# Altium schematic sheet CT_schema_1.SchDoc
size 612 x 583 mm
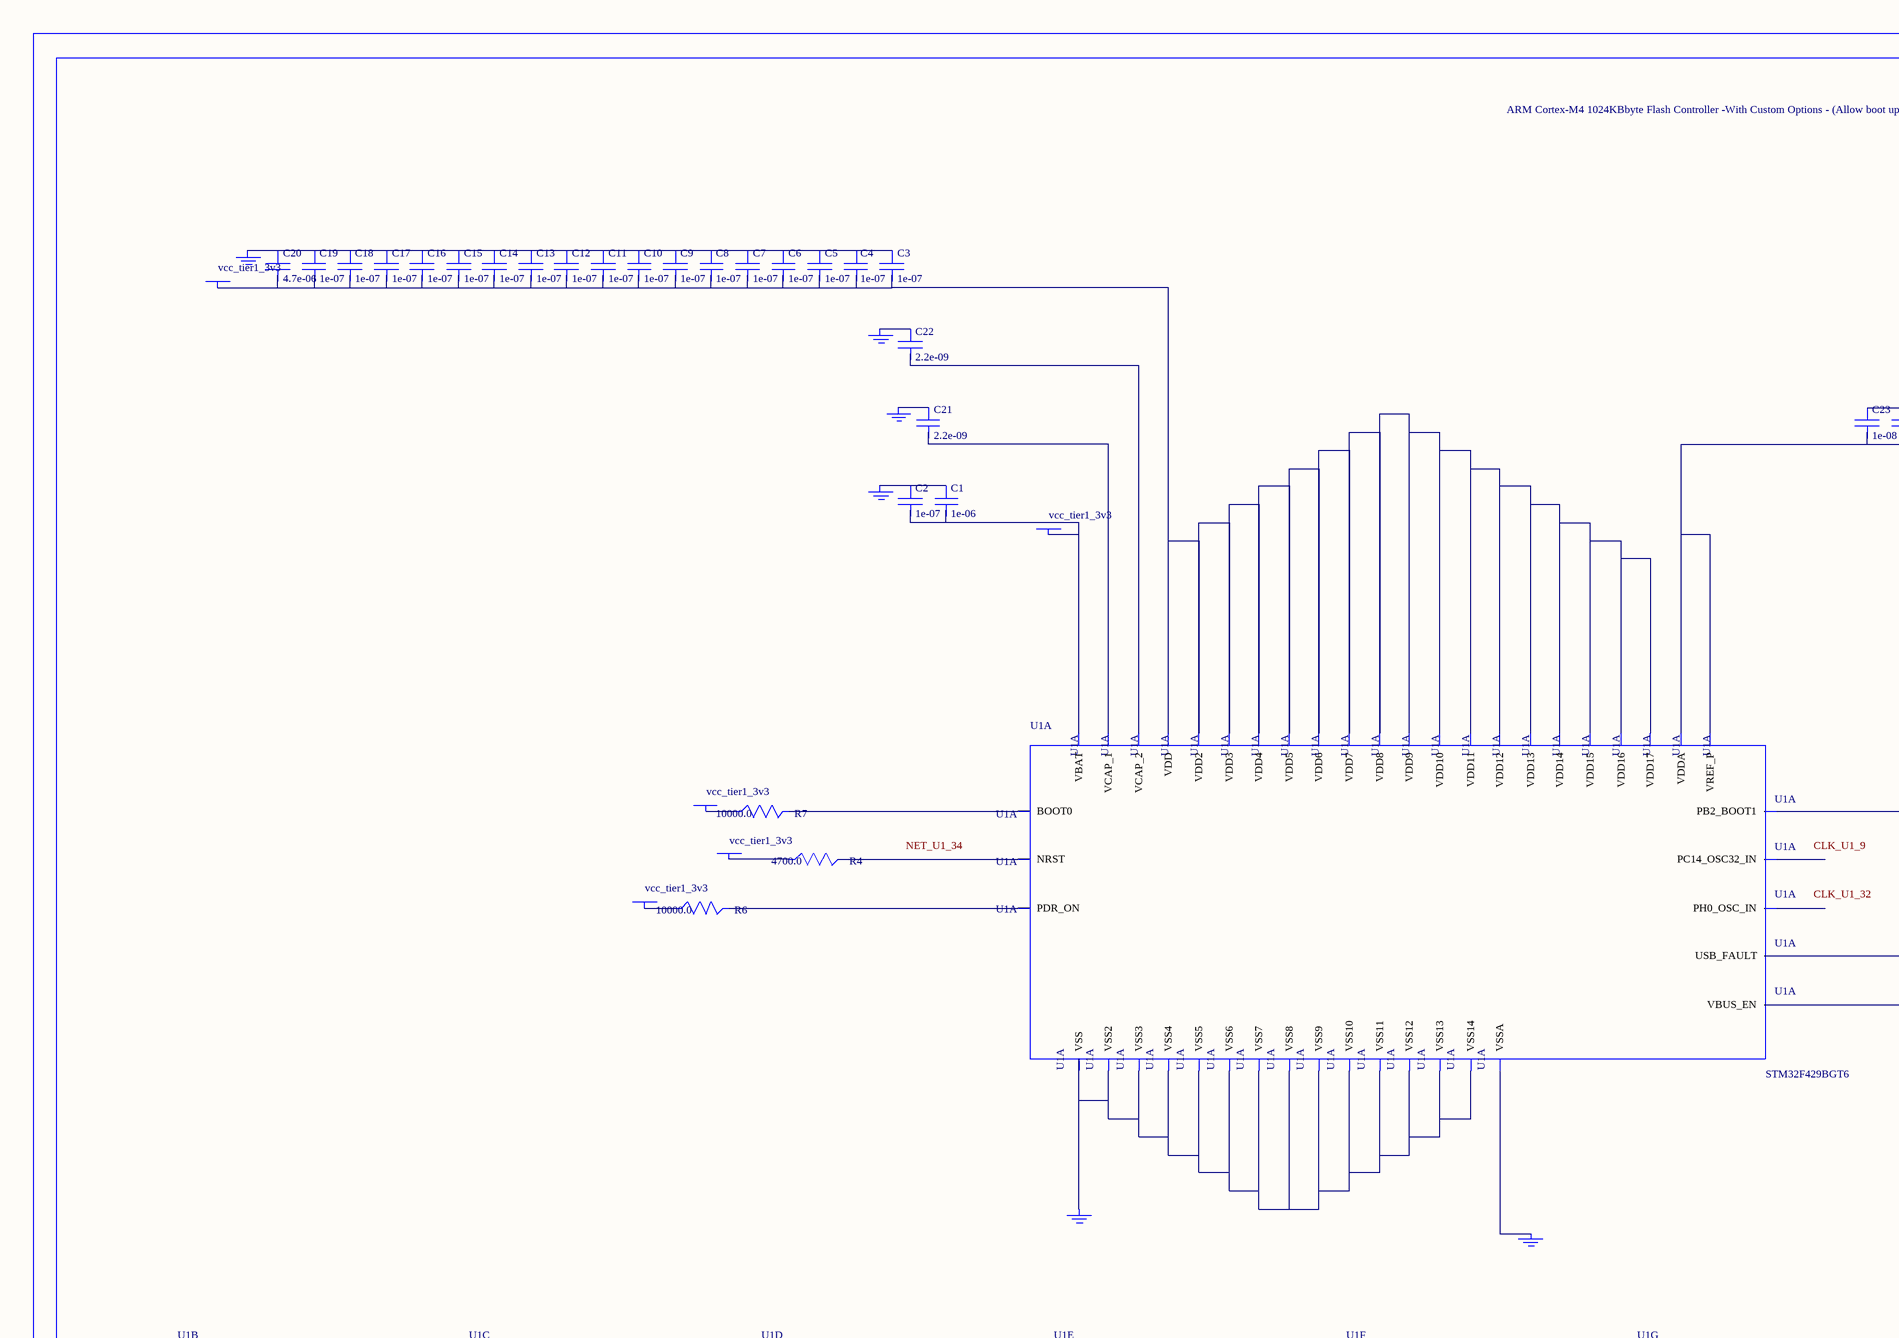
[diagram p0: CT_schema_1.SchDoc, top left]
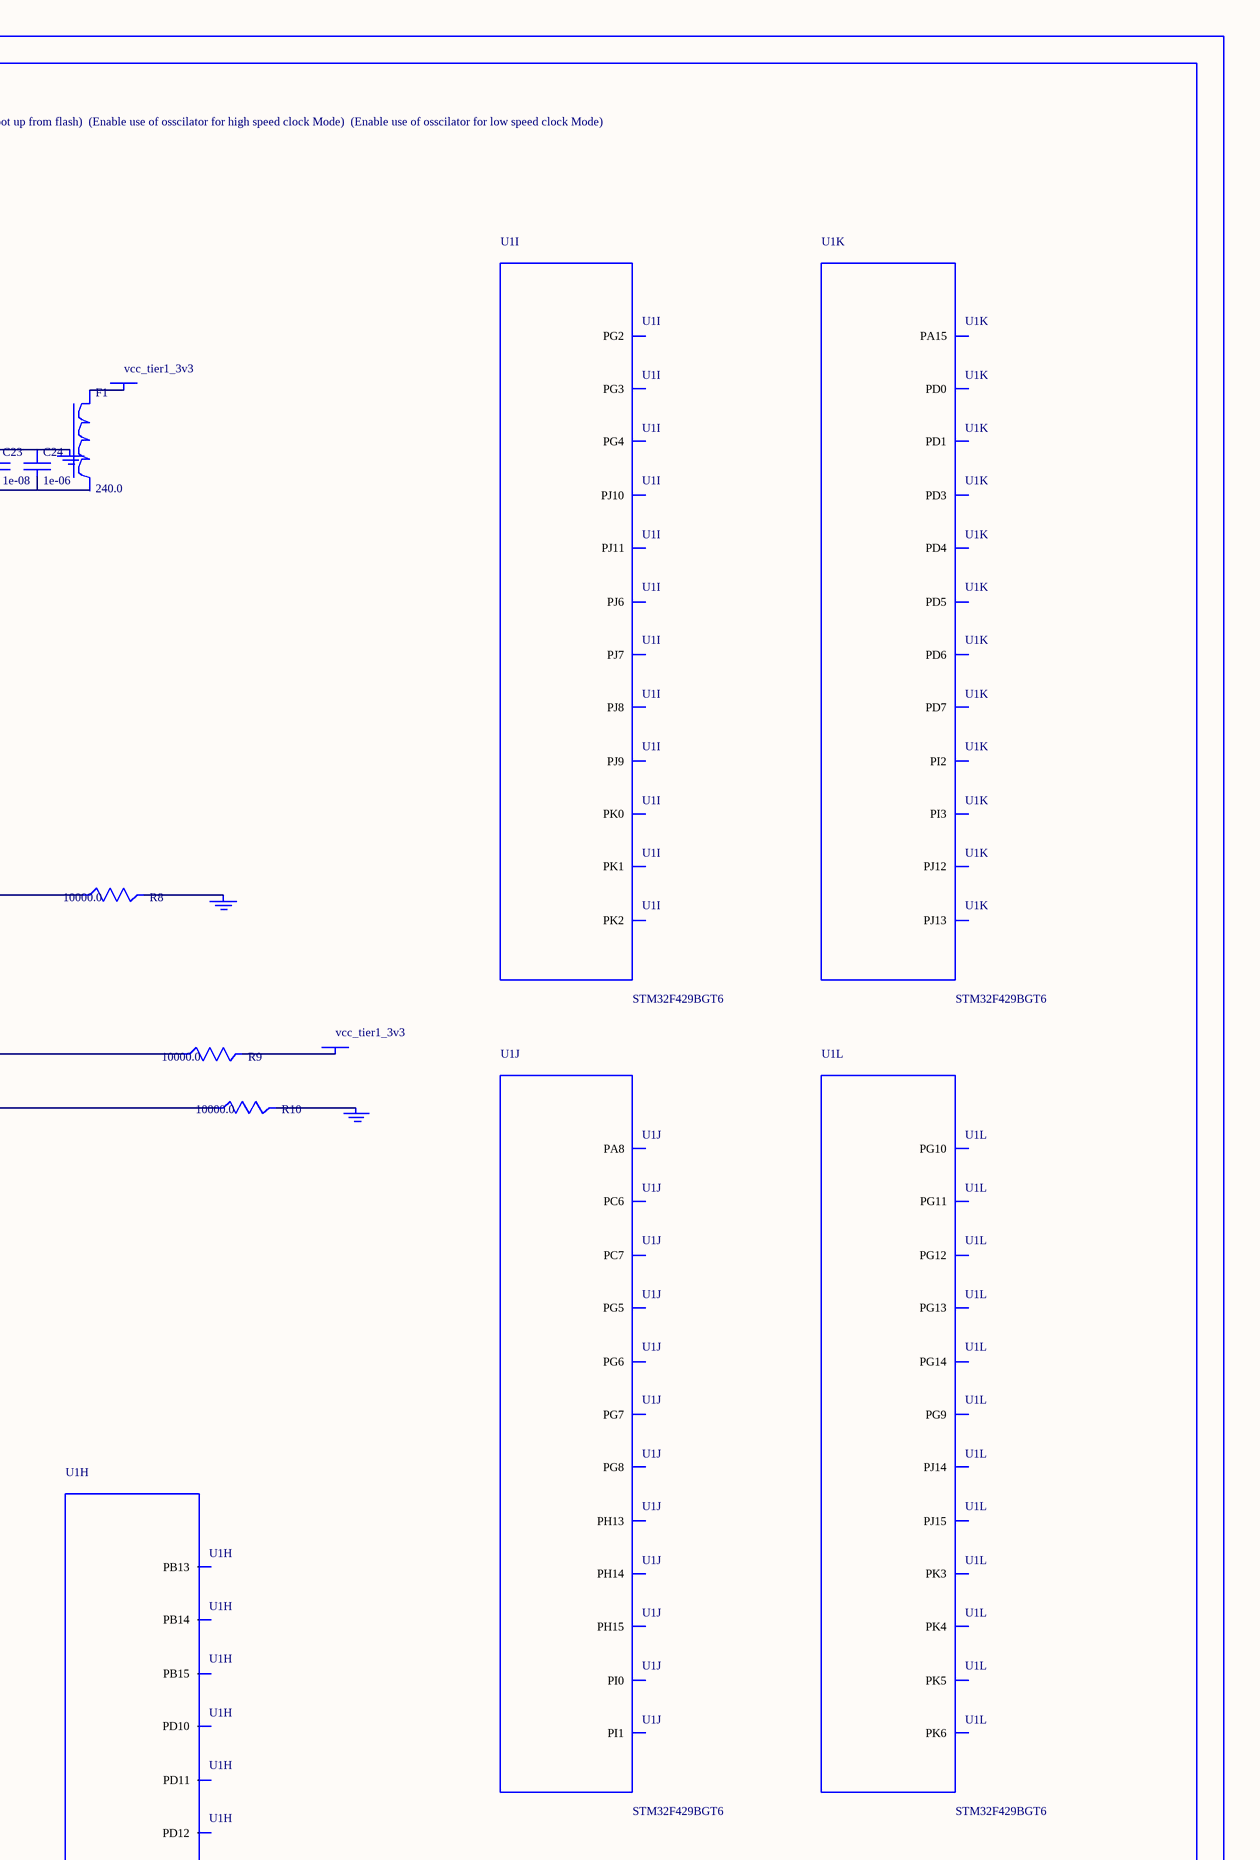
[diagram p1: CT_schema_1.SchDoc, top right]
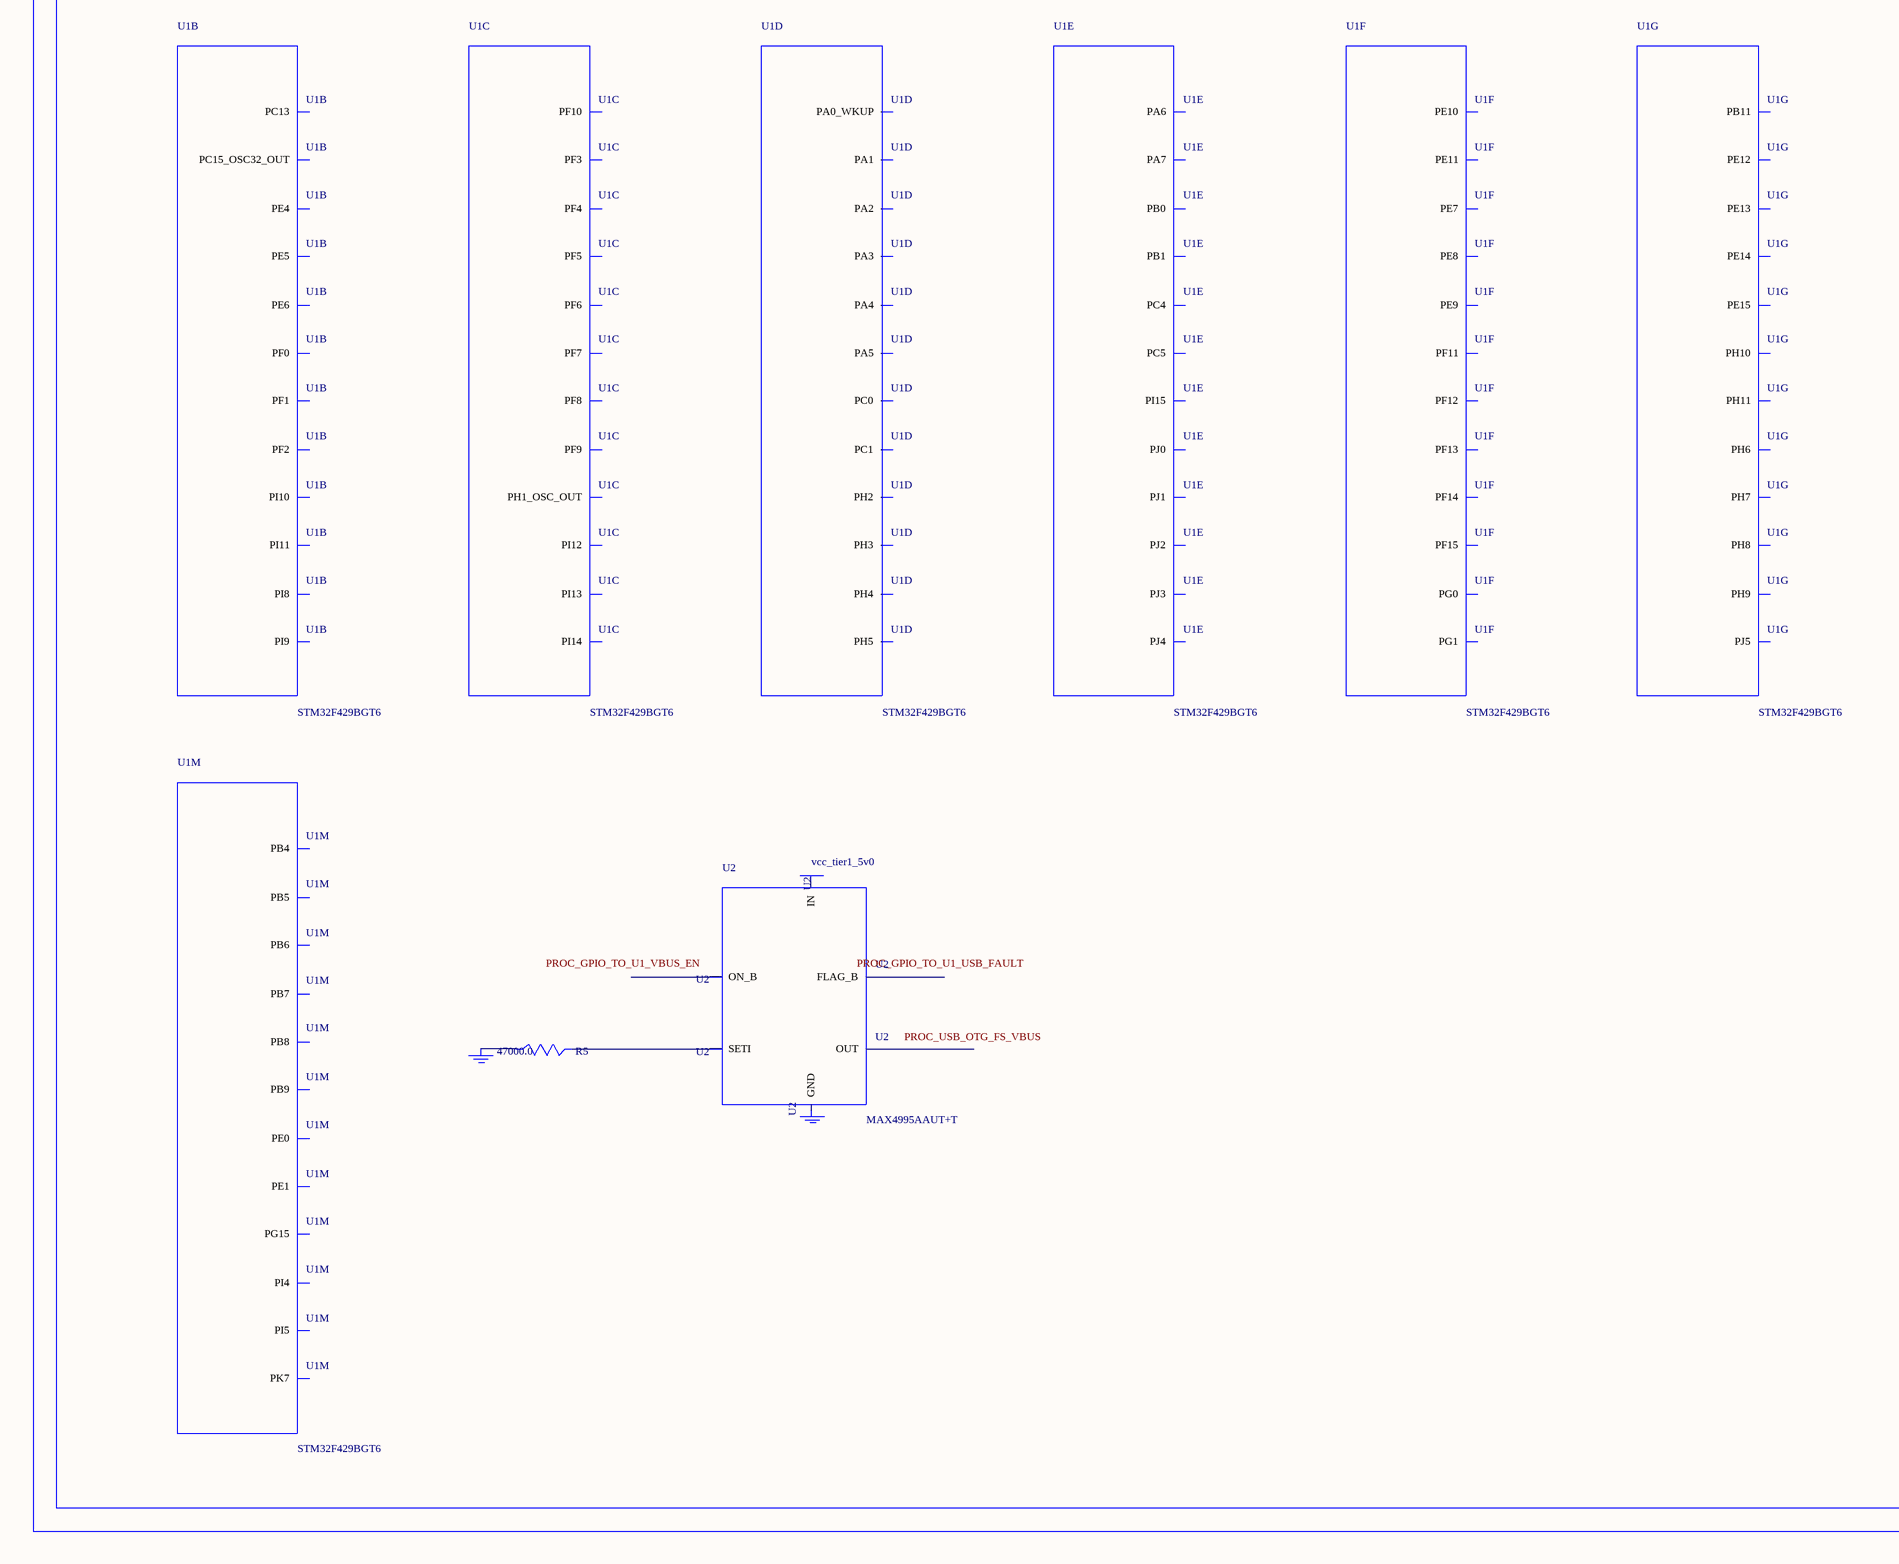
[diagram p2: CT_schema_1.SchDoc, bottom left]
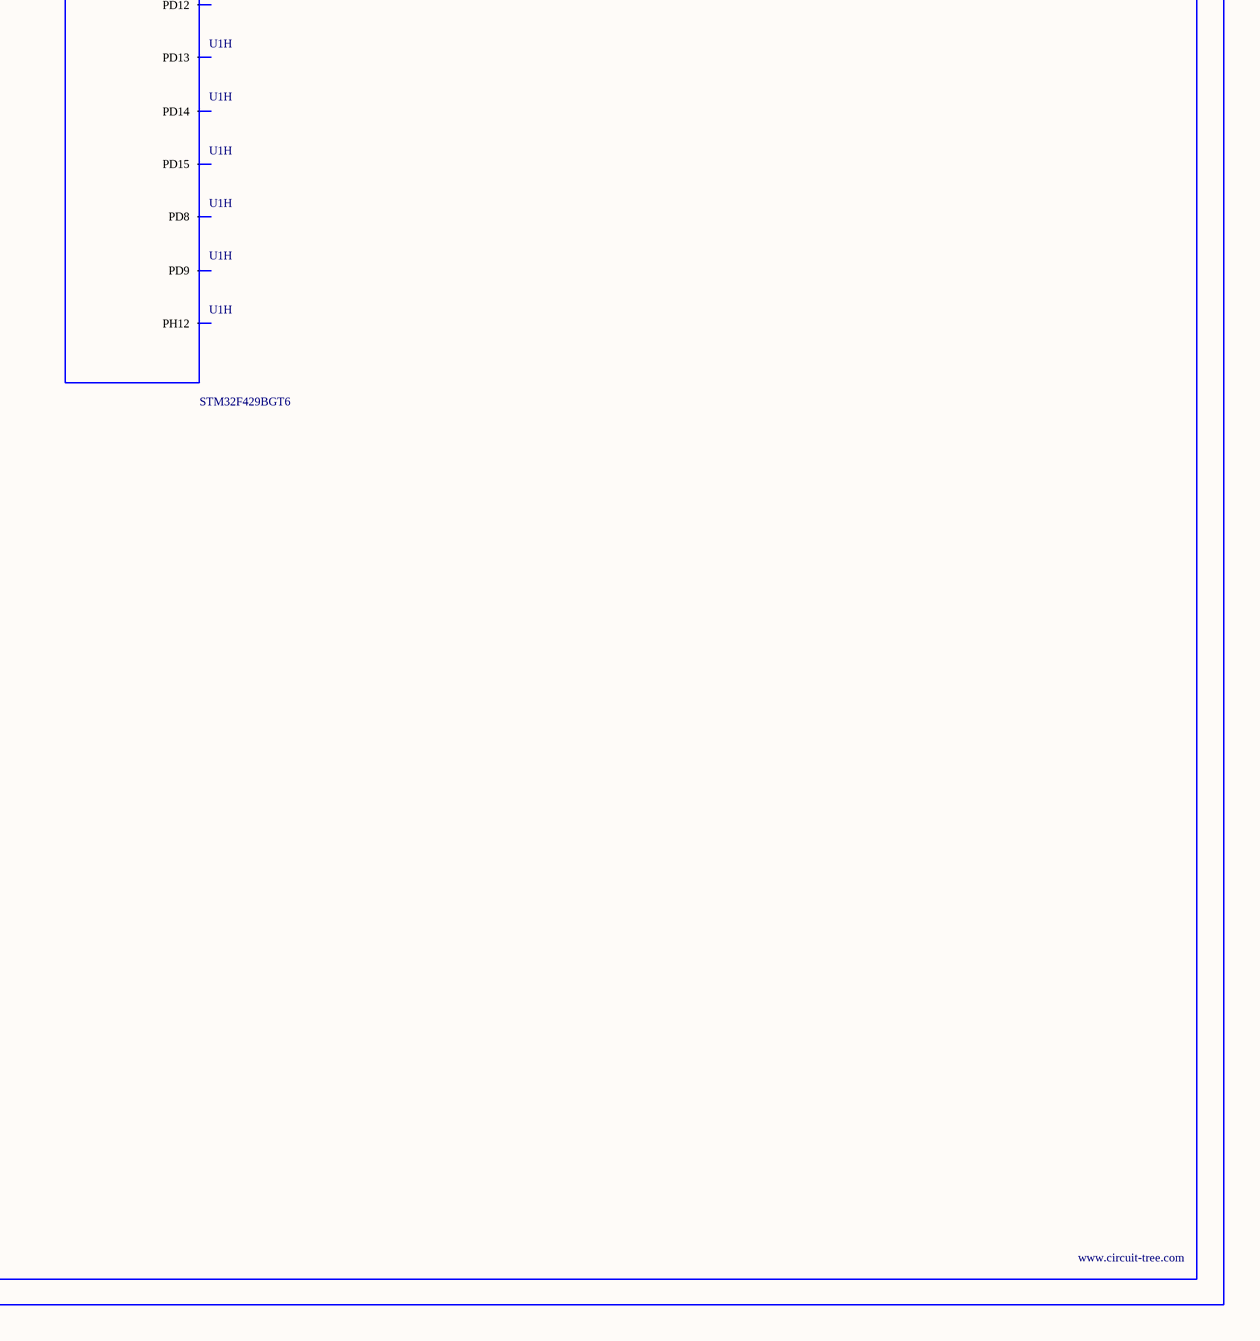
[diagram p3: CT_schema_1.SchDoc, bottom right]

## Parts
BORDER0  (no value)
C1  1e-06  [C0603]
C2  1e-07  [C0603]
C3  1e-07  [C0603]
C4  1e-07  [C0603]
C5  1e-07  [C0603]
C6  1e-07  [C0603]
C7  1e-07  [C0603]
C8  1e-07  [C0603]
C9  1e-07  [C0603]
C10  1e-07  [C0603]
C11  1e-07  [C0603]
C12  1e-07  [C0603]
C13  1e-07  [C0603]
C14  1e-07  [C0603]
C15  1e-07  [C0603]
C16  1e-07  [C0603]
C17  1e-07  [C0603]
C18  1e-07  [C0603]
C19  1e-07  [C0603]
C20  4.7e-06  [C0603]
C21  2.2e-09  [C0603]
C22  2.2e-09  [C0603]
C23  1e-08  [C0603]
C24  1e-06  [C0603]
F1  240.0  [L0603]
GND_INSTANCE_0_0  (no value)
GND_INSTANCE_0_1  (no value)
GND_INSTANCE_0_2  (no value)
GND_INSTANCE_0_3  (no value)
GND_INSTANCE_0_4  (no value)
GND_INSTANCE_0_5  (no value)
GND_INSTANCE_0_6  (no value)
GND_INSTANCE_0_7  (no value)
GND_INSTANCE_0_8  (no value)
GND_INSTANCE_0_9  (no value)
GND_INSTANCE_0_10  (no value)
POWER_INSTANCE_0_0  vcc_tier1_3v3
POWER_INSTANCE_0_1  vcc_tier1_3v3
POWER_INSTANCE_0_2  vcc_tier1_3v3
POWER_INSTANCE_0_3  vcc_tier1_3v3
POWER_INSTANCE_0_4  vcc_tier1_3v3
POWER_INSTANCE_0_5  vcc_tier1_3v3
POWER_INSTANCE_0_6  vcc_tier1_3v3
POWER_INSTANCE_0_7  vcc_tier1_5v0
R4  4700.0  [R0603]
R5  47000.0  [R0603]
R6  10000.0  [R0603]
R7  10000.0  [R0603]
R8  10000.0  [R0603]
R9  10000.0  [R0603]
R10  10000.0  [R0603]
U1  STM32F429BGT6  [LQFP208]  (parts A,B,C,D,E,F,G,H,I,J,K,L,M of 17)
U2  MAX4995AAUT+T  [SOT-23-6]

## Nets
NetC1_1: C1.1 C2.1 GND_INSTANCE_0_1.0(GND)
NetC1_2: C1.2 C2.2 POWER_INSTANCE_0_1.0(PWR) U1.6(VBAT)
NetC3_1: C3.1 C4.1 C5.1 C6.1 C7.1 C8.1 C9.1 C10.1 C11.1 C12.1 C13.1 C14.1 C15.1 C16.1 C17.1 C18.1 C19.1 C20.1 GND_INSTANCE_0_2.0(GND)
NetC3_2: C3.2 C4.2 C5.2 C6.2 C7.2 C8.2 C9.2 C10.2 C11.2 C12.2 C13.2 C14.2 C15.2 C16.2 C17.2 C18.2 C19.2 C20.2 POWER_INSTANCE_0_2.0(PWR) U1.15(VDD) U1.26(VDD2) U1.39(VDD3) U1.52(VDD4) U1.59(VDD5) U1.73(VDD6) U1.83(VDD7) U1.94(VDD8) U1.103(VDD9) U1.115(VDD10) U1.124(VDD11) U1.137(VDD12) U1.150(VDD13) U1.158(VDD14) U1.171(VDD15) U1.185(VDD16) U1.204(VDD17)
NetC21_1: C21.1 GND_INSTANCE_0_6.0(GND)
NetC21_2: C21.2 U1.92(VCAP_1)
NetC22_1: C22.1 GND_INSTANCE_0_7.0(GND)
NetC22_2: C22.2 U1.148(VCAP_2)
NetC23_1: C23.1 C24.1 GND_INSTANCE_0_4.0(GND)
NetC23_2: C23.2 C24.2 U1.41(VREF_P) U1.42(VDDA)
NetF1_1: F1.1 POWER_INSTANCE_0_3.0(PWR)
NetGND_INSTANCE_0_0_0: GND_INSTANCE_0_0.0(GND) R10.2
NetGND_INSTANCE_0_3_0: GND_INSTANCE_0_3.0(GND) U1.40(VSSA)
NetGND_INSTANCE_0_5_0: GND_INSTANCE_0_5.0(GND) R8.2
NetGND_INSTANCE_0_8_0: GND_INSTANCE_0_8.0(GND) U1.14(VSS) U1.25(VSS2) U1.51(VSS3) U1.60(VSS4) U1.72(VSS5) U1.82(VSS6) U1.93(VSS7) U1.114(VSS8) U1.125(VSS9) U1.136(VSS10) U1.149(VSS11) U1.170(VSS12) U1.184(VSS13) U1.202(VSS14)
NetGND_INSTANCE_0_9_0: GND_INSTANCE_0_9.0(GND) R5.1
NetPOWER_INSTANCE_0_0_0: POWER_INSTANCE_0_0.0(PWR) R9.2
NetPOWER_INSTANCE_0_4_0: POWER_INSTANCE_0_4.0(PWR) R7.1
NetPOWER_INSTANCE_0_5_0: POWER_INSTANCE_0_5.0(PWR) R6.1
NetPOWER_INSTANCE_0_6_0: POWER_INSTANCE_0_6.0(PWR) R4.1
NetR4_2: R4.2 U1.34(NRST)
NetR5_2: R5.2 U2.3(SETI)
NetR6_2: R6.2 U1.203(PDR_ON)
NetR7_2: R7.2 U1.197(BOOT0)
NetR8_1: R8.1 U1.63(PB2_BOOT1)
NetR9_1: R9.1 U1.2(USB_FAULT)
NetR10_1: R10.1 U1.1(VBUS_EN)

Not connected (* = marked no-connect by the designer): F1 2; GND_INSTANCE_0_10 0(GND); POWER_INSTANCE_0_7 0(PWR); U1 3(PE4) 4(PE5) 5(PE6) 7(PI8) 8(PC13) 9(PC14_OSC32_IN) 10(PC15_OSC32_OUT) 11(PI9) 12(PI10) 13(PI11) 16(PF0) 17(PF1) 18(PF2) 19(PI12) 20(PI13) 21(PI14) 22(PF3) 23(PF4) 24(PF5) 27(PF6) 28(PF7) 29(PF8) 30(PF9) 31(PF10) 32(PH0_OSC_IN) 33(PH1_OSC_OUT) 35(PC0) 36(PC1) 43(PA0_WKUP) 44(PA1) 45(PA2) 46(PH2) 47(PH3) 48(PH4) 49(PH5) 50(PA3) 53(PA4) 54(PA5) 55(PA6) 56(PA7) 57(PC4) 58(PC5) 61(PB0) 62(PB1) 64(PI15) 65(PJ0) 66(PJ1) 67(PJ2) 68(PJ3) 69(PJ4) 70(PF11) 71(PF12) 74(PF13) 75(PF14) 76(PF15) 77(PG0) 78(PG1) 79(PE7) 80(PE8) 81(PE9) 84(PE10) 85(PE11) 86(PE12) 87(PE13) 88(PE14) 89(PE15) 91(PB11) 95(PJ5) 96(PH6) 97(PH7) 98(PH8) 99(PH9) 100(PH10) 101(PH11) 102(PH12) 105(PB13) 106(PB14) 107(PB15) 108(PD8) 109(PD9) 110(PD10) 111(PD11) 112(PD12) 113(PD13) 116(PD14) 117(PD15) 118(PJ6) 119(PJ7) 120(PJ8) 121(PJ9) 122(PJ10) 123(PJ11) 126(PK0) 127(PK1) 128(PK2) 129(PG2) 130(PG3) 131(PG4) 132(PG5) 133(PG6) 134(PG7) 135(PG8) 138(PC6) 139(PC7) 142(PA8) 151(PH13) 152(PH14) 153(PH15) 154(PI0) 155(PI1) 156(PI2) 157(PI3) 160(PA15) 164(PD0) 165(PD1) 167(PD3) 168(PD4) 169(PD5) 172(PD6) 173(PD7) 174(PJ12) 175(PJ13) 176(PJ14) 177(PJ15) 178(PG9) 179(PG10) 180(PG11) 181(PG12) 182(PG13) 183(PG14) 186(PK3) 187(PK4) 188(PK5) 189(PK6) 190(PK7) 191(PG15) 193(PB4) 194(PB5) 195(PB6) 196(PB7) 198(PB8) 199(PB9) 200(PE0) 201(PE1) 205(PI4) 206(PI5); U2 1(OUT) 2(GND) 4(ON_B) 5(IN) 6(FLAG_B)

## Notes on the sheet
- Labels drawn without touching a wire or pin: CLK_U1_9, CLK_U1_32, NET_U1_34, PROC_GPIO_TO_U1_USB_FAULT, PROC_GPIO_TO_U1_VBUS_EN, PROC_USB_OTG_FS_VBUS

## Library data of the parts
BORDER0 = BORDER_PAGE0
C1 C24 = C0603C105K3RACTU
C2-C19 = 06035C104K4Z2A
C20 = GRM188R6YA475KE15D
C21 C22 = 06031C222KAZ2A
C23 = 06035C103K4Z2A
F1 = Z0603C241ASMST
GND_INSTANCE_0_0-GND_INSTANCE_0_10 = GND
POWER_INSTANCE_0_0-POWER_INSTANCE_0_7 = PWR
R4 = RC0603JR-074K7L
R5 = RC0603JR-0747KL
R6-R10 = RC0603JR-0710KL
